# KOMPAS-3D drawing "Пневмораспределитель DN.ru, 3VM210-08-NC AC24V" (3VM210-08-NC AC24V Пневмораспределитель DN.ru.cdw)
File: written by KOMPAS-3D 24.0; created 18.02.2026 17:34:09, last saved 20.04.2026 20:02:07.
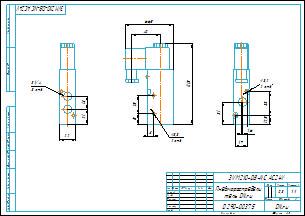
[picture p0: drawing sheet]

Document properties: Автор: R2D2; Форматы листов документа: A3; Полное имя файла: 3VM210-08-NC AC24V Пневмораспределитель DN.ru.m3d; Масса: 0.3; Наименование: Пневмораспределитель DN.ru; Количество листов документа: 1; Примечание: D290-00375

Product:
- Part/product: Пневмораспределитель DN.ru  | designation 3VM210-08-NC AC24V
    Масса: 0.3
    Раздел спецификации: Прочие изделия
    Примечание: D290-00375

Views: Вид 1, Спереди, Проекционный вид 2, Проекционный вид 3
Referenced files in E:\Работа\Зайцев\Аксессуары для пневмоприводов\Пневмораспределители DN.ru\3VM210-06-NC Пневмораспределитель DN.RU\AC24V\: 3VM210-06-NC AC24V Пневмораспределитель DN.ru.m3d
Referenced files in E:\Работа\Зайцев\Аксессуары для пневмоприводов\Пневмораспределители DN.ru\3VM210-08-NC Пневмораспределитель DN.RU\AC24V\: 3VM210-08-NC AC24V Пневмораспределитель DN.ru.m3d
Referenced files in E:\Работа\Зайцев\Для компаса\: чертеж DN.ru А3.cdt
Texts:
  чертеж DN.ru А3.cdt
  Пневмораспредели
  тель DN.ru
  Пневмораспределитель DN.ru
  3VM210-08-NC AC24V Пневмораспределитель DN.ru
Dimensions and other numbers on the sheet: 0; 3; 2; 4; 3 отв.; 21; 18; 22; 3VM210-08-NC AC24V; 66,5; 40; 111,5; 3,3; 2 отв.; 15; 25; 8; 9; 3,2; 33; 12,5; 17; 1,6; 31; 6; 1:1; 1; 0,3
